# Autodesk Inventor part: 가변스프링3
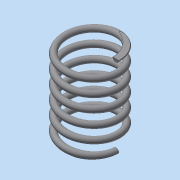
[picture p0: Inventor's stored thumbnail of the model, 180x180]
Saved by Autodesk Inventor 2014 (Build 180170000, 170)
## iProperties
Created: 2023-01
Part Number: 가변스프링3
Material: 스테인레스 스틸
Document SubType Name: Modeling
Designer: dg
Density: 8.08 g/cm^3
Appearance: 반연마
Mass: 8.00312 g
Surface Area: 20.0941 cm^2
Volume: 0.990485 cm^3
Author: dg
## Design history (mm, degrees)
sketch "스케치1"
  geometry: L1 (0, 0)-(0, 26.33); L2 (0, 0)-(8.5, 0); L3 (0, 26.33)-(8.5, 26.33); C1 r 1 at (8.5, 0)
  constraints: 6 end point, 1 centre point, 1 coincident, 1 parallel, 1 perpendicular, 1 vertical, 1 vertical alignment
  dimensions: "d0" = 26.33013 distance of L1.start L1.end (derived); "d1" = 8.5 distance of L1.start L2.end; "d2" = 2 diameter of C1
feature "코일1" pitch "d3" = 10; turns "d5" = 6; dims "d4" = 26.33013 (= d0), "d6" = 0, angle "d7" = 90 deg, angle "d8" = 90 deg, "d9" = 0, "d10" = 0
node "작업 평면1"
node "작업 평면2"
feature "분할1"
feature "분할2"
node "솔리드1"
other parameters: "d11" = 0, "d12" = 0
